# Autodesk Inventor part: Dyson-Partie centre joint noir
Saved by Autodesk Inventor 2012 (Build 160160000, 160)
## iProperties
Created: 2012-11
Part Number: Dyson-Partie centre joint noir
Material: Default
Document SubType Name: Modeling
Designer: Administrateur
Density: 1 g/cm^3
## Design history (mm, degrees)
node "Dyson-Partie centre joint noir1"
node "Dyson-Partie centre joint noir"
node "Base1"
